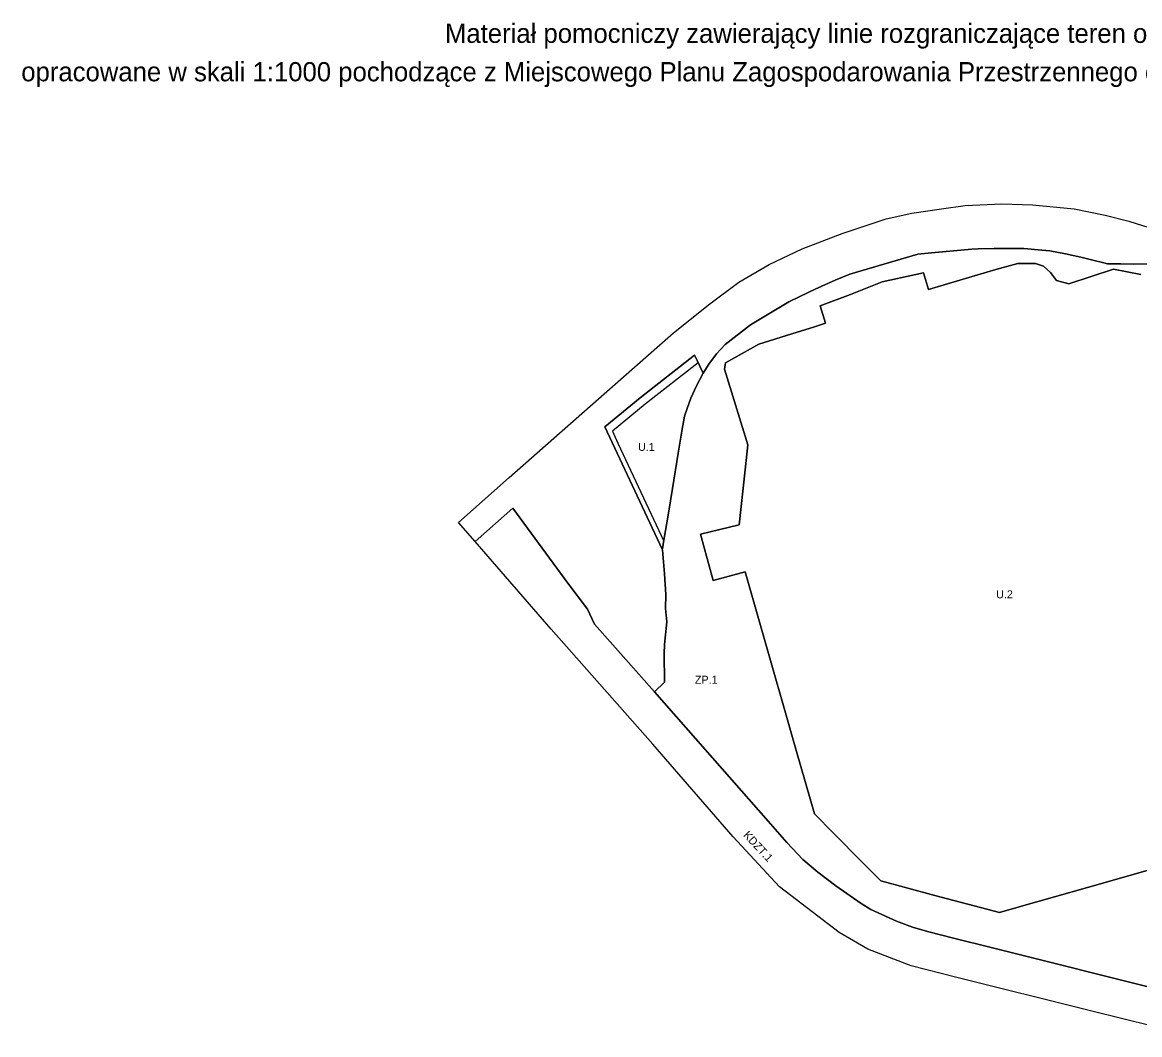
# Model space of a CAD drawing. Extents: x 7429178 to 7430831, y 5550228 to 5551611.
# Drawn here: x 7429178 to 7429876, y 5550979 to 5551611 of the extents above; entities that cross this region are included whole.
import ezdxf

# ---------------------------------------------------------------- set-up
doc = ezdxf.new("R2010")
doc.units = 0
for name, color, linetype in [('info', 7, 'Continuous'), ('linie rozgraniczające', 7, 'Continuous'), ('nieprzekraczalne linie zabudowy', 7, 'Continuous'), ('przeznaczenia terenów', 7, 'Continuous')]:
    doc.layers.add(name, color=color, linetype=linetype)

msp = doc.modelspace()

# ---------------------------------------------------------------- linework, layer by layer
at = {"layer": 'linie rozgraniczające'}
for points in [[(7429882.93, 5551460.46), (7429872.08, 5551460.34), (7429864.42, 5551460.47), (7429856.06, 5551460.47), (7429853.84, 5551461.11), (7429846.85, 5551462.91), (7429839.44, 5551464.81), (7429829.92, 5551466.72), (7429820.08, 5551468.62), (7429815, 5551469.05), (7429803.87, 5551470.05), (7429785.34, 5551470.24), (7429775.38, 5551469.91), (7429771.34, 5551469.77), (7429746.12, 5551467.39), (7429737.5, 5551466.58), (7429695.17, 5551454.03), (7429685.89, 5551450.31), (7429673.53, 5551444.72), (7429669.52, 5551442.9), (7429656.97, 5551436.77), (7429632.96, 5551422.38), (7429617.21, 5551410.12), (7429611.7, 5551404.39), (7429607.02, 5551397.85), (7429603.41, 5551392.18), (7429599.65, 5551400.21), (7429598.12, 5551403.46), (7429564.15, 5551376.74), (7429542.11, 5551358.73), (7429577.81, 5551282.38), (7429578.03, 5551281.91), (7429579.35, 5551266.98), (7429580.11, 5551254.01), (7429579.85, 5551245.22), (7429580.8, 5551236.96), (7429579.3, 5551222.68), (7429579.2, 5551217.11), (7429579.32, 5551199.23), (7429573.07, 5551193.21), (7429535.55, 5551235.39), (7429531.19, 5551244.9), (7429518.84, 5551261.11), (7429484.58, 5551307.99), (7429460.93, 5551287.17), (7429450.63, 5551299.04), (7429482.31, 5551327.01), (7429538.14, 5551376.29), (7429585.04, 5551417.35), (7429607.68, 5551435.66), (7429625.71, 5551449.11), (7429644.68, 5551460.05), (7429665.35, 5551469.96), (7429690.24, 5551479.49), (7429717.87, 5551488.71), (7429733.9, 5551492.27), (7429752.39, 5551495.01), (7429767.13, 5551497.1), (7429790.05, 5551497.98), (7429809.21, 5551497.47), (7429835.28, 5551495.03), (7429854.58, 5551491.03), (7429869.41, 5551487.14), (7429893.85, 5551479.52)], [(7429887.28, 5551007.37), (7429848.25, 5551017.16), (7429829.18, 5551021.94), (7429782.57, 5551033.63), (7429760.7, 5551039.11), (7429743.68, 5551043.45), (7429734.33, 5551046.22), (7429724.35, 5551049.94), (7429708.32, 5551057.25), (7429702.25, 5551060.82), (7429686.27, 5551071.95), (7429675.17, 5551080.42), (7429665.77, 5551088.41), (7429655.77, 5551098.93), (7429644.09, 5551112.25), (7429592.7, 5551170.84), (7429573.07, 5551193.21), (7429579.32, 5551199.23), (7429579.2, 5551217.11), (7429579.3, 5551222.68), (7429580.8, 5551236.96), (7429579.85, 5551245.22), (7429580.11, 5551254.01), (7429579.35, 5551266.98), (7429578.03, 5551281.91), (7429577.81, 5551282.38), (7429578.03, 5551282.43), (7429578.93, 5551287.96), (7429581.72, 5551304.87), (7429584.25, 5551320.2), (7429587.91, 5551342.31), (7429590.16, 5551355.95), (7429591.71, 5551365.31), (7429593.38, 5551370.11), (7429595.67, 5551376.71), (7429599.41, 5551384.36), (7429603.41, 5551392.18), (7429607.02, 5551397.85), (7429611.7, 5551404.39), (7429617.21, 5551410.12), (7429632.96, 5551422.38), (7429656.97, 5551436.77), (7429669.52, 5551442.9), (7429673.53, 5551444.72), (7429685.89, 5551450.31), (7429695.17, 5551454.03), (7429737.5, 5551466.58), (7429746.12, 5551467.39), (7429771.34, 5551469.77), (7429775.38, 5551469.91), (7429785.34, 5551470.24), (7429803.87, 5551470.05), (7429815, 5551469.05), (7429820.08, 5551468.62), (7429829.92, 5551466.72), (7429839.44, 5551464.81), (7429846.85, 5551462.91), (7429853.84, 5551461.11), (7429856.06, 5551460.47), (7429864.42, 5551460.47), (7429872.08, 5551460.34), (7429882.93, 5551460.46)], [(7429885.24, 5551082.78), (7429843.5, 5551070.94), (7429802.46, 5551059.29), (7429788.53, 5551055.33), (7429748.15, 5551065.95), (7429714.4, 5551075.01), (7429702.82, 5551086.75), (7429684.89, 5551104.92), (7429673.09, 5551116.87), (7429661.84, 5551155.94), (7429652.81, 5551187.3), (7429648.05, 5551203.89), (7429639.31, 5551234.62), (7429629.77, 5551268.1), (7429609.73, 5551262.76), (7429601.76, 5551291.57), (7429626.04, 5551297.58), (7429629.76, 5551331.83), (7429631.46, 5551347.46), (7429616.83, 5551394.66), (7429617.37, 5551398.75), (7429638.24, 5551410.38), (7429658.95, 5551416.81), (7429673.13, 5551421.25), (7429679.85, 5551423.43), (7429676.65, 5551434.31), (7429695.44, 5551441.39), (7429715.27, 5551449.37), (7429736.3, 5551453.85), (7429741.19, 5551454.9), (7429744.19, 5551444.56), (7429763.91, 5551450.44), (7429786.3, 5551457.11), (7429800.11, 5551460.7), (7429811.17, 5551460.79), (7429816.07, 5551459.16), (7429820.51, 5551455.17), (7429824.14, 5551450.09), (7429832.02, 5551448.1), (7429859.94, 5551457.16), (7429876.86, 5551453.97)], [(7429876.86, 5551453.97), (7429859.94, 5551457.16), (7429832.02, 5551448.1), (7429824.14, 5551450.09), (7429820.51, 5551455.17), (7429816.07, 5551459.16), (7429811.17, 5551460.79), (7429800.11, 5551460.7), (7429786.3, 5551457.11), (7429763.91, 5551450.44), (7429744.19, 5551444.56), (7429741.19, 5551454.9), (7429736.3, 5551453.85), (7429715.27, 5551449.37), (7429695.44, 5551441.39), (7429676.65, 5551434.31), (7429679.85, 5551423.43), (7429673.13, 5551421.25), (7429658.95, 5551416.81), (7429638.24, 5551410.38), (7429617.37, 5551398.75), (7429616.83, 5551394.66), (7429631.46, 5551347.46), (7429629.76, 5551331.83), (7429626.04, 5551297.58), (7429601.76, 5551291.57), (7429609.73, 5551262.76), (7429629.77, 5551268.1), (7429639.31, 5551234.62), (7429648.05, 5551203.89), (7429652.81, 5551187.3), (7429661.84, 5551155.94), (7429673.09, 5551116.87), (7429684.89, 5551104.92), (7429702.82, 5551086.75), (7429714.4, 5551075.01), (7429748.15, 5551065.95), (7429788.53, 5551055.33), (7429802.46, 5551059.29), (7429843.5, 5551070.94), (7429885.24, 5551082.78)], [(7429905.17, 5550978.96), (7429844.7, 5550993.98), (7429761.1, 5551014.82), (7429733.42, 5551022.04), (7429706.38, 5551032.46), (7429688.48, 5551042.85), (7429651.2, 5551071.26), (7429622.13, 5551102.52), (7429571.96, 5551160.45), (7429508.43, 5551232.41), (7429460.93, 5551287.17), (7429484.58, 5551307.99), (7429518.84, 5551261.11), (7429531.19, 5551244.9), (7429535.55, 5551235.39), (7429573.07, 5551193.21), (7429592.7, 5551170.84), (7429644.09, 5551112.25), (7429655.77, 5551098.93), (7429665.77, 5551088.41), (7429675.17, 5551080.42), (7429686.27, 5551071.95), (7429702.25, 5551060.82), (7429708.32, 5551057.25), (7429724.35, 5551049.94), (7429734.33, 5551046.22), (7429743.68, 5551043.45), (7429760.7, 5551039.11), (7429782.57, 5551033.63), (7429829.18, 5551021.94), (7429848.25, 5551017.16), (7429887.28, 5551007.37)]]:
    msp.add_lwpolyline(points, dxfattribs=at)
msp.add_lwpolyline([(7429577.81, 5551282.38), (7429577.81, 5551282.38), (7429542.11, 5551358.73), (7429564.15, 5551376.74), (7429598.12, 5551403.46), (7429599.65, 5551400.21), (7429603.41, 5551392.18), (7429599.41, 5551384.36), (7429595.67, 5551376.71), (7429593.38, 5551370.11), (7429591.71, 5551365.31), (7429590.16, 5551355.95), (7429587.91, 5551342.31), (7429584.25, 5551320.2), (7429581.72, 5551304.87), (7429578.93, 5551287.96), (7429578.03, 5551282.43)], close=True, dxfattribs=at)
at = {"layer": 'nieprzekraczalne linie zabudowy'}
msp.add_lwpolyline([(7429600.3, 5551398.81), (7429567.28, 5551372.84), (7429546.79, 5551356.1), (7429550.22, 5551348.56), (7429578.83, 5551287.3)], dxfattribs=at)

# ---------------------------------------------------------------- texts
at = {"layer": 'info'}
for s, p in [('Materiał pomocniczy zawierający linie rozgraniczające teren o różnym przeznaczeniu i różnych warunkach zagospodarowania terenu, ', (7429442.16, 5551598.6)), ('opracowane w skali 1:1000 pochodzące z Miejscowego Planu Zagospodarowania Przestrzennego obszaru "Bieńczyce - Szpital" zatwierdzonego uchwałą RMK Nr LV/1126/16 z dnia 26 października 2016 r.', (7429177.44, 5551574.6))]:
    msp.add_text(s, height=12, dxfattribs=at).set_placement(p)
at = {"layer": 'przeznaczenia terenów'}
for s, p in [('U.1', (7429562.82, 5551343.72)), ('U.2', (7429786.55, 5551251.58)), ('ZP.1', (7429598.3, 5551198.19))]:
    msp.add_text(s, height=5, dxfattribs=at).set_placement(p)
msp.add_text('KDZT.1', height=5, rotation=312.94152, dxfattribs=at).set_placement((7429628.2, 5551103.32))

doc.saveas('drawing.dxf')
